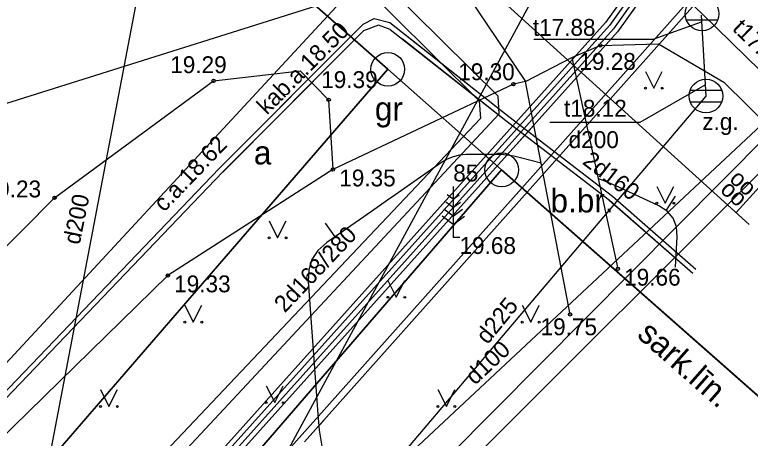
# Model space of a CAD drawing. Extents: x 532933 to 533143, y 328014 to 328163.
# Drawn here: x 533014.71 to 533036.51, y 328096.56 to 328109.11 of the extents above; entities that cross this region are included whole.
import ezdxf

# ---------------------------------------------------------------- set-up
doc = ezdxf.new("R2010")
doc.units = 0
for name, color, linetype in [('APGR_ELEM_####_####_#', 7, 'Continuous'), ('APGR_SARK_####_####_#', 7, 'Continuous'), ('APGR_SARK_####_TKST_#', 7, 'Continuous'), ('APGS_VADV_ZSPR_####_#', 7, 'Continuous'), ('CELI_CAPM_####_####_#', 7, 'Continuous'), ('CELI_CMAL_####_####_#', 7, 'Continuous'), ('CELI_CSEG_####_TKST_#', 7, 'Continuous'), ('CELI_SEGL_####_####_#', 7, 'Continuous'), ('ELEK_ACRL_####_####_#', 7, 'Continuous'), ('ELEK_ACRL_####_TKST_#', 7, 'Continuous'), ('ELEK_VADP_VSPR_####_I', 7, 'Continuous'), ('ELEK_VADP_VSPR_TKST_I', 7, 'Continuous'), ('ELEK_VADP_ZSPR_####_#', 7, 'Continuous'), ('LKAN_ELEM_####_####_#', 7, 'Continuous'), ('LKAN_ELEM_PAST_TKST_#', 7, 'Continuous'), ('LKAN_VADP_PAST_####_#', 7, 'Continuous'), ('LKAN_VADP_PAST_TKST_#', 7, 'Continuous'), ('RAMI_UZMR_####_####_#', 7, 'Continuous'), ('RELJ_AATZ_####_TKST_#', 7, 'Continuous'), ('RELJ_ELEM_####_####_#', 7, 'Continuous'), ('RELJ_HORZ_PAMT_####_#', 7, 'Continuous'), ('ROBZ_PROJ_####_####_#', 7, 'Continuous'), ('ROBZ_UZMR_####_####_#', 7, 'Continuous'), ('SAKK_IZVK_####_TKST_#', 7, 'Continuous'), ('SAKK_KKAN_####_####_#', 7, 'Continuous'), ('SILT_VADP_UDEN_####_#', 7, 'Continuous'), ('SILT_VADP_UDEN_TKST_#', 7, 'Continuous'), ('SKAN_VADP_PAST_####_#', 7, 'Continuous'), ('SKAN_VADP_PAST_TKST_#', 7, 'Continuous'), ('TERT_DIAM_####_TKST_#', 7, 'Continuous'), ('TERT_ELEM_####_####_#', 7, 'Continuous'), ('UDTK_VADP_UDEN_####_#', 7, 'Continuous'), ('UDTK_VADP_UDEN_TKST_#', 7, 'Continuous')]:
    doc.layers.add(name, color=color, linetype=linetype)

msp = doc.modelspace()

# ---------------------------------------------------------------- linework, layer by layer
at = {"layer": 'APGR_ELEM_####_####_#'}
for centre in [(533025.763, 328107.492), (533029.138, 328104.514)]:
    msp.add_circle(centre, 0.5, dxfattribs=at)
at = {"layer": 'APGR_SARK_####_####_#'}
for p, q in [((533025.763, 328107.492), (532984.275, 328144.093)), ((533029.138, 328104.514), (533025.763, 328107.492)), ((533036.096, 328098.376), (533029.138, 328104.514))]:
    msp.add_line(p, q, dxfattribs=at)
at = {"layer": 'APGS_VADV_ZSPR_####_#'}
msp.add_lwpolyline([(533035.157, 328119.006), (533019.905, 328090.862), (533000, 328068.423)], dxfattribs=at)
at = {"layer": 'CELI_CAPM_####_####_#'}
msp.add_lwpolyline([(533031.218, 328107.846), (533032.06, 328108.202), (533033.785, 328108.244), (533035.723, 328107.108), (533037.113, 328105.736)], dxfattribs=at)
at = {"layer": 'CELI_CMAL_####_####_#'}
for p, q in [((533029.844, 328107.131), (533031.218, 328107.846)), ((533031.218, 328107.846), (533032.582, 328101.582)), ((533024.139, 328104.523), (533019.246, 328101.385)), ((533019.246, 328101.385), (533013.532, 328095.798))]:
    msp.add_line(p, q, dxfattribs=at)
for points in [[(533012.863, 328105.989), (533027.507, 328110.598)], [(533029.484, 328107.052), (533024.139, 328104.523)], [(533031.165, 328100.229), (533029.844, 328107.131), (533029.484, 328107.052)]]:
    msp.add_lwpolyline(points, dxfattribs=at)
at = {"layer": 'CELI_SEGL_####_####_#'}
for p, q in [((533027.507, 328110.598), (533029.844, 328107.131)), ((533020.601, 328107.151), (533023.163, 328107.451)), ((533023.163, 328107.451), (533024.011, 328106.592)), ((533024.011, 328106.592), (533024.139, 328104.523))]:
    msp.add_line(p, q, dxfattribs=at)
msp.add_lwpolyline([(533011.521, 328092.239), (533007.24, 328084.661), (533003.535, 328084.875), (533003.518, 328086.539), (533005.617, 328089.34), (533010.142, 328097.887), (533015.888, 328103.687), (533020.601, 328107.151)], dxfattribs=at)
at = {"layer": 'ELEK_ACRL_####_####_#'}
for points in [[(533026.185, 328108.402), (533029.258, 328105.979)], [(533026.278, 328108.52), (533029.351, 328106.097)], [(533020.765, 328104.555), (533024.354, 328108.152)], [(533020.871, 328104.449), (533024.46, 328108.046)], [(533029.26, 328105.978), (533032.334, 328103.613)], [(533029.351, 328106.097), (533032.425, 328103.732)], [(533013.203, 328096.663), (533020.765, 328104.555)], [(533013.311, 328096.559), (533020.873, 328104.451)], [(533032.326, 328103.619), (533034.807, 328101.448)], [(533032.425, 328103.732), (533034.894, 328101.572)]]:
    msp.add_lwpolyline(points, dxfattribs=at)
at = {"layer": 'ELEK_VADP_VSPR_####_I'}
for points in [[(533025.03, 328108.829), (533025.363, 328108.996), (533025.826, 328108.877)], [(533000, 328082.63), (533000.322, 328083.149), (533002.47, 328085.498), (533013.203, 328096.663), (533020.765, 328104.555), (533025.03, 328108.829)], [(533025.838, 328108.676), (533025.487, 328108.802), (533025.042, 328108.629)], [(533025.826, 328108.877), (533029.351, 328106.097), (533032.425, 328103.732), (533034.894, 328101.572)], [(533000, 328082.346), (533000.442, 328083.058), (533002.579, 328085.395), (533013.311, 328096.559), (533020.872, 328104.45), (533025.042, 328108.629)], [(533025.838, 328108.676), (533029.259, 328105.979), (533032.33, 328103.616), (533034.807, 328101.448)]]:
    msp.add_lwpolyline(points, dxfattribs=at)
at = {"layer": 'ELEK_VADP_ZSPR_####_#'}
for p, q in [((533036.815, 328115.38), (533032.22, 328108.88)), ((533037.01, 328115.397), (533032.337, 328108.786)), ((533037.205, 328115.414), (533032.454, 328108.692)), ((533037.401, 328115.43), (533032.572, 328108.599)), ((533023.296, 328096.452), (533036.041, 328110.746)), ((533023.302, 328096.761), (533035.769, 328110.742)), ((533032.22, 328108.88), (533015.093, 328089.804)), ((533032.337, 328108.786), (533015.206, 328089.706)), ((533032.454, 328108.692), (533015.32, 328089.608)), ((533032.572, 328108.599), (533015.494, 328089.577))]:
    msp.add_line(p, q, dxfattribs=at)
for points in [[(533029.579, 328105.267), (533030.121, 328105.869)], [(533023.742, 328096.952), (533023.865, 328097.09)], [(533016.226, 328088.824), (533023.302, 328096.761)]]:
    msp.add_lwpolyline(points, dxfattribs=at)
at = {"layer": 'LKAN_ELEM_####_####_#'}
for p, q in [((533034.609, 328108.96), (533035.545, 328108.96)), ((533034.724, 328106.876), (533035.66, 328106.876)), ((533034.724, 328106.526), (533035.66, 328106.526))]:
    msp.add_line(p, q, dxfattribs=at)
for centre in [(533035.077, 328109.135), (533035.192, 328106.701)]:
    msp.add_circle(centre, 0.5, dxfattribs=at)
at = {"layer": 'LKAN_VADP_PAST_####_#'}
for p, q in [((533035.048, 328109.097), (533035.192, 328106.701)), ((533035.192, 328106.701), (533014.324, 328082.094))]:
    msp.add_line(p, q, dxfattribs=at)
msp.add_lwpolyline([(533000, 328144.172), (533010.252, 328132.804), (533025.892, 328117.826), (533035.077, 328109.135), (533038.53, 328105.77)], dxfattribs=at)
at = {"layer": 'LKAN_VADP_PAST_TKST_#'}
for p, q in [((533033.627, 328108.386), (533035.06, 328108.902)), ((533030.093, 328108.386), (533033.627, 328108.386)), ((533033.245, 328105.925), (533035.172, 328107.035)), ((533030.567, 328105.925), (533033.245, 328105.925))]:
    msp.add_line(p, q, dxfattribs=at)
at = {"layer": 'RAMI_UZMR_####_####_#'}
msp.add_lwpolyline([(532947.854, 328059.458), (532970.012, 328105.269), (532980.164, 328130.66), (532983.041, 328140.509), (533003.397, 328153.917), (533034.71, 328122.623), (533045.001, 328112.629), (533020.332, 328088.009), (533039.378, 328069.977), (533029.682, 328029.753), (533016.724, 328021.343), (532947.854, 328059.458)], dxfattribs=at)
at = {"layer": 'RELJ_ELEM_####_####_#'}
for centre in [(533032.06, 328108.202), (533020.601, 328107.151), (533029.484, 328107.052), (533024.011, 328106.592), (533024.139, 328104.523), (533015.888, 328103.687), (533032.582, 328101.582), (533019.247, 328101.385), (533031.165, 328100.229)]:
    msp.add_circle(centre, 0.05, dxfattribs=at)
at = {"layer": 'RELJ_HORZ_PAMT_####_#'}
for p, q in [((533034.275, 328103.737), (533034.009, 328103.314)), ((533023.911, 328102.935), (533024.197, 328102.524))]:
    msp.add_line(p, q, dxfattribs=at)
for points in [[(533030.308, 328104.716), (533029.693, 328104.874), (533029.497, 328104.918), (533029.299, 328104.949), (533029.099, 328104.967), (533028.898, 328104.971), (533028.09, 328104.964), (533027.892, 328104.947), (533027.704, 328104.903), (533027.525, 328104.83), (533027.354, 328104.728), (533026.241, 328103.95), (533026, 328103.781), (533025.759, 328103.613), (533025.518, 328103.445), (533025.277, 328103.277), (533023.955, 328102.356), (533023.695, 328102.127), (533023.517, 328101.859), (533023.421, 328101.552), (533023.406, 328101.206), (533023.686, 328097.272), (533023.706, 328097.035), (533023.733, 328096.798), (533023.766, 328096.563), (533023.806, 328096.328)], [(533034.289, 328101.628), (533034.342, 328102.527), (533034.322, 328102.828), (533034.224, 328103.082), (533034.047, 328103.29), (533033.791, 328103.45), (533032.613, 328103.999), (533032.316, 328104.129), (533032.013, 328104.246), (533032.005, 328104.248)]]:
    msp.add_lwpolyline(points, dxfattribs=at)
at = {"layer": 'ROBZ_PROJ_####_####_#'}
for p, q in [((533025.763, 328107.492), (532984.275, 328144.093)), ((533029.138, 328104.514), (533025.763, 328107.492)), ((533038.5, 328096.255), (533029.138, 328104.514))]:
    msp.add_line(p, q, dxfattribs=at)
at = {"layer": 'ROBZ_UZMR_####_####_#'}
for p, q in [((532984.275, 328144.093), (533025.763, 328107.492)), ((533025.763, 328107.492), (533001.874, 328079.871))]:
    msp.add_line(p, q, dxfattribs=at)
msp.add_lwpolyline([(532993.949, 328071.405), (532999.253, 328076.841), (533001.874, 328079.871), (533025.763, 328107.492), (533029.138, 328104.514), (533014.917, 328088.072), (533037.903, 328068.645), (533030.421, 328036.082)], close=True, dxfattribs=at)
msp.add_lwpolyline([(533030.97, 328020.652), (533020.389, 328026.352), (533029.157, 328030.58), (533030.421, 328036.082), (533037.903, 328068.645), (533014.917, 328088.072), (533029.138, 328104.514), (533038.98, 328095.831)], dxfattribs=at)
at = {"layer": 'SAKK_IZVK_####_TKST_#'}
msp.add_line((533036.088, 328103.248), (533036.783, 328104.015), dxfattribs=at)
at = {"layer": 'SAKK_KKAN_####_####_#'}
msp.add_line((533026.568, 328111.881), (532996.716, 328079.621), dxfattribs=at)
msp.add_lwpolyline([(533000, 328138.237), (533026.568, 328111.881), (533036.477, 328102.895)], dxfattribs=at)
at = {"layer": 'SILT_VADP_UDEN_####_#'}
for points in [[(533004.853, 328045.947), (533019.384, 328034.966), (533019.749, 328035.185), (533031.003, 328047.839), (533031.356, 328048.225), (533031.335, 328048.654), (533025.793, 328053.779), (533025.755, 328054.215), (533035.838, 328064.377), (533036.105, 328064.808), (533033.176, 328075.216), (533032.836, 328076.021), (533015.446, 328091.145), (533015.462, 328091.585), (533029.065, 328106.172), (533029.033, 328106.692), (533017.302, 328118.3), (533000, 328134.38)], [(533000, 328133.784), (533016.764, 328118.182), (533028.476, 328106.559), (533028.508, 328106.039), (533014.85, 328091.596), (533014.892, 328091.077), (533032.527, 328075.724), (533032.689, 328075.239), (533035.542, 328065.283), (533035.311, 328064.711), (533024.98, 328054.226), (533025.028, 328053.821), (533027.938, 328051.227), (533030.653, 328048.689), (533030.642, 328048.162), (533019.754, 328035.526), (533019.215, 328035.483), (533005.473, 328047.022)]]:
    msp.add_lwpolyline(points, dxfattribs=at)
at = {"layer": 'SKAN_VADP_PAST_####_#'}
msp.add_lwpolyline([(533018.885, 328112.548), (533015.334, 328093.891), (533000, 328076.986)], dxfattribs=at)
at = {"layer": 'TERT_ELEM_####_####_#'}
for p, q in [((533033.397, 328107.431), (533033.647, 328106.931)), ((533033.647, 328106.931), (533033.897, 328107.431)), ((533027.703, 328104.021), (533027.703, 328102.521)), ((533033.738, 328104.024), (533033.988, 328103.524)), ((533033.988, 328103.524), (533034.238, 328104.024)), ((533027.703, 328103.645), (533027.527, 328103.773)), ((533027.703, 328103.645), (533027.877, 328103.773)), ((533027.703, 328103.395), (533027.487, 328103.553)), ((533027.703, 328103.395), (533027.919, 328103.553)), ((533027.703, 328103.145), (533027.425, 328103.349)), ((533027.703, 328103.145), (533027.981, 328103.349)), ((533027.703, 328102.895), (533027.371, 328103.139)), ((533027.703, 328102.895), (533028.037, 328103.139)), ((533022.25, 328103), (533022.5, 328102.5)), ((533022.5, 328102.5), (533022.75, 328103)), ((533027.703, 328102.521), (533027.903, 328102.521)), ((533025.765, 328101.236), (533026.015, 328100.736)), ((533026.015, 328100.736), (533026.265, 328101.236)), ((533019.75, 328100.5), (533020, 328100)), ((533020, 328100), (533020.25, 328100.5)), ((533029.75, 328100.5), (533030, 328100)), ((533030, 328100), (533030.25, 328100.5)), ((533022.163, 328098.115), (533022.413, 328097.615)), ((533022.413, 328097.615), (533022.663, 328098.115)), ((533017.25, 328098), (533017.5, 328097.5)), ((533017.5, 328097.5), (533017.75, 328098)), ((533027.25, 328098), (533027.5, 328097.5)), ((533027.5, 328097.5), (533027.75, 328098))]:
    msp.add_line(p, q, dxfattribs=at)
for centre, radius in [((533033.397, 328106.931), 0.028), ((533033.897, 328106.931), 0.0263), ((533033.738, 328103.523), 0.028), ((533034.238, 328103.523), 0.0263), ((533022.25, 328102.5), 0.028), ((533022.75, 328102.5), 0.0263), ((533025.765, 328100.736), 0.028), ((533026.265, 328100.736), 0.0263), ((533019.75, 328100), 0.028), ((533020.25, 328100), 0.0263), ((533029.75, 328100), 0.028), ((533030.25, 328100), 0.0263), ((533017.25, 328097.5), 0.028), ((533017.75, 328097.5), 0.0263), ((533022.163, 328097.615), 0.028), ((533022.663, 328097.615), 0.0263), ((533027.25, 328097.5), 0.028), ((533027.75, 328097.5), 0.0263)]:
    msp.add_circle(centre, radius, dxfattribs=at)
at = {"layer": 'UDTK_VADP_UDEN_####_#'}
msp.add_line((533038.939, 328107.482), (533011.851, 328080.208), dxfattribs=at)
msp.add_lwpolyline([(533010.744, 328081.458), (533040.624, 328109.383), (533024.808, 328124.378), (533000, 328150.276)], dxfattribs=at)

# ---------------------------------------------------------------- texts
at = {"layer": 'APGR_SARK_####_TKST_#'}
msp.add_text('sark.līn.', height=0.7, rotation=318.581, dxfattribs=at).set_placement((533033.119, 328099.582))
at = {"layer": 'CELI_CSEG_####_TKST_#'}
for s, p in [('gr', (533025.38, 328105.975)), ('a', (533021.794, 328104.673)), ('b.br.', (533030.583, 328103.251))]:
    msp.add_text(s, height=0.7, dxfattribs=at).set_placement(p)
at = {"layer": 'ELEK_ACRL_####_TKST_#'}
for s, rotation, p in [('c.a.18.62', 46.2233, (533019.133, 328103.242)), ('2d160', 322.4269, (533031.503, 328104.709))]:
    msp.add_text(s, height=0.5, rotation=rotation, dxfattribs=at).set_placement(p)
at = {"layer": 'ELEK_VADP_VSPR_TKST_I'}
msp.add_text('kab.a.18.50', height=0.5, rotation=45.0638, dxfattribs=at).set_placement((533022.183, 328106.119))
at = {"layer": 'LKAN_ELEM_PAST_TKST_#'}
msp.add_text('z.g.', height=0.5, dxfattribs=at).set_placement((533035.083, 328105.694))
at = {"layer": 'LKAN_VADP_PAST_TKST_#'}
for s, p in [('t17.88', (533030.061, 328108.484)), ('t18.12', (533030.986, 328106.089)), ('d200', (533031.123, 328105.159))]:
    msp.add_text(s, height=0.5, dxfattribs=at).set_placement(p)
for s, rotation, p in [('t17.42', 315.8258, (533035.948, 328108.673)), ('d225', 50.7705, (533028.719, 328099.319))]:
    msp.add_text(s, height=0.5, rotation=rotation, dxfattribs=at).set_placement(p)
at = {"layer": 'RELJ_AATZ_####_TKST_#'}
for s, p in [(' 19.28', (533031.256, 328107.475)), (' 19.29', (533019.131, 328107.379)), (' 19.30', (533027.666, 328107.17)), (' 19.39', (533023.604, 328106.937)), (' 19.35', (533024.139, 328104.023)), (' 19.23', (533013.631, 328103.697)), (' 19.68', (533027.703, 328102.021)), (' 19.66', (533032.582, 328101.082)), (' 19.33', (533019.247, 328100.885)), (' 19.75', (533030.105, 328099.613))]:
    msp.add_text(s, height=0.5, dxfattribs=at).set_placement(p)
at = {"layer": 'SAKK_IZVK_####_TKST_#'}
for p in [(533035.857, 328104.201), (533035.585, 328103.884)]:
    msp.add_text('oo', height=0.5, rotation=317.7972, dxfattribs=at).set_placement(p)
at = {"layer": 'SILT_VADP_UDEN_TKST_#'}
msp.add_text('2d168/280', height=0.5, rotation=46.6001, dxfattribs=at).set_placement((533022.71, 328100.255))
at = {"layer": 'SKAN_VADP_PAST_TKST_#'}
msp.add_text('d200', height=0.5, rotation=78.5175, dxfattribs=at).set_placement((533016.631, 328102.277))
at = {"layer": 'TERT_DIAM_####_TKST_#'}
msp.add_text('85', height=0.5, dxfattribs=at).set_placement((533027.703, 328104.171))
at = {"layer": 'UDTK_VADP_UDEN_TKST_#'}
msp.add_text('d100', height=0.5, rotation=43.0629, dxfattribs=at).set_placement((533028.348, 328098.116))

doc.saveas('drawing.dxf')
